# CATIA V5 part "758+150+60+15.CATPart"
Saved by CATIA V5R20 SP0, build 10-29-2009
Part number: 758+150+60+15
Revision: TUTTO
Definition: NON CONOSCIUTO
Nomenclature: 758+150+60+15
Source: Unknown
Bounding box of the stored display mesh (mm): x -75 to 75, y 0 to 60, z -75 to 75
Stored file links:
  C:\Users\Utente\Desktop\IO LAVORO\3D X SITO CF\X 3D SITO CF 27-09-2020\758\758+150+60+15.CATPart
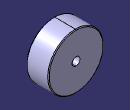
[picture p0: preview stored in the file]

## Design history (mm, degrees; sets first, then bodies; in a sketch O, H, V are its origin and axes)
Body1 "Importato1" (main body)
  Solid1: solid without history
